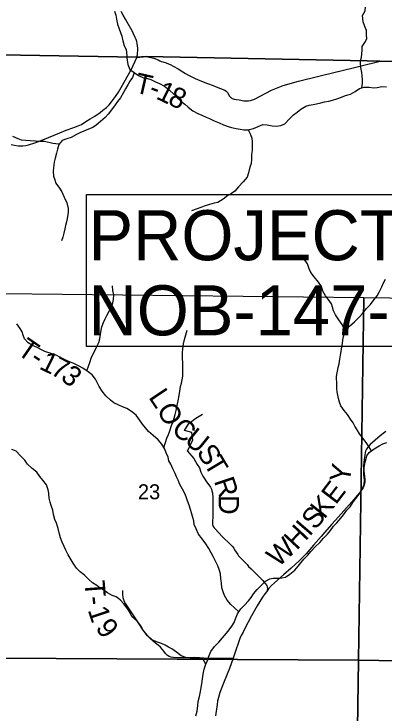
# Model space of a CAD drawing. Extents: x 0 to 34, y -8.9 to 22.
# Drawn here: x 24.734 to 25.769, y 10.111 to 12.069 of the extents above; entities that cross this region are included whole.
import ezdxf

# ---------------------------------------------------------------- set-up
doc = ezdxf.new("R2010")
doc.units = 0
for name, color, linetype in [('GM_X_Corporation', 7, 'Continuous'), ('GM_X_County_Road', 7, 'Continuous'), ('GM_X_County_Road_Text', 7, 'Continuous'), ('GM_X_Minor_River', 7, 'Continuous'), ('GM_X_Section_Text', 7, 'Continuous'), ('GM_X_Township_Road', 7, 'Continuous'), ('GM_X_Township_Road_Text', 7, 'Continuous'), ('SH_Masking', 7, 'Continuous'), ('SH_Text', 7, 'Continuous')]:
    doc.layers.add(name, color=color, linetype=linetype)

msp = doc.modelspace()

# ---------------------------------------------------------------- linework, layer by layer
at = {"layer": 'GM_X_Corporation'}
for points in [[(28.8143, 13.904), (23.7167, 13.904), (23.7167, 11.9654), (24.1849, 11.9621), (24.2054, 11.9625), (24.3163, 11.9608), (25.0773, 11.948), (25.1035, 11.9505), (25.7218, 11.9377), (25.7578, 11.9372), (26.2139, 11.9314), (27.1396, 11.9157), (27.9423, 11.8981), (28.2591, 11.8967), (28.3241, 11.8942), (28.4085, 11.8914), (28.4711, 11.8911), (28.692, 11.888), (28.7762, 11.8872), (28.7779, 11.9899), (28.7786, 12.0342), (28.7787, 12.0377), (28.8049, 13.053), (28.8122, 13.7561)], [(28.8143, 13.904), (23.7167, 13.904), (23.7167, 11.9654), (24.1849, 11.9621), (24.2054, 11.9625), (24.3163, 11.9608), (25.0773, 11.948), (25.1035, 11.9505), (25.7218, 11.9377), (25.7578, 11.9372), (26.2139, 11.9314), (27.1396, 11.9157), (27.9423, 11.8981), (28.2591, 11.8967), (28.3241, 11.8942), (28.4085, 11.8914), (28.4711, 11.8911), (28.692, 11.888), (28.7762, 11.8872), (28.7779, 11.9899), (28.7786, 12.0342), (28.7787, 12.0377), (28.8049, 13.053), (28.8122, 13.7561)], [(24.6992, 11.287), (25.7123, 11.2765), (25.698, 10.2614), (24.6816, 10.2678)], [(25.7123, 11.2765), (26.7259, 11.2629), (26.7158, 10.2453), (25.698, 10.2614)], [(24.6816, 10.2678), (25.698, 10.2614), (25.683, 9.2467), (24.6733, 9.2562)], [(25.698, 10.2614), (26.7158, 10.2453), (26.7025, 9.2378), (25.683, 9.2467)]]:
    msp.add_lwpolyline(points, close=True, dxfattribs=at)
for points in [[(27.1396, 11.9157), (26.2139, 11.9314), (25.7578, 11.9372), (25.7218, 11.9377), (25.1035, 11.9505), (25.0773, 11.948), (24.3163, 11.9608), (24.2054, 11.9625), (24.1849, 11.9621), (23.7167, 11.9654), (23.7167, 7.104)], [(27.1396, 11.9157), (26.2139, 11.9314), (25.7578, 11.9372), (25.7218, 11.9377), (25.1035, 11.9505), (25.0773, 11.948), (24.3163, 11.9608), (24.2054, 11.9625), (24.2028, 11.8378), (24.2025, 11.824), (24.2007, 11.7362), (24.1845, 10.7587), (24.1844, 10.755), (24.1596, 9.2636)]]:
    msp.add_lwpolyline(points, dxfattribs=at)
at = {"layer": 'GM_X_County_Road'}
for points in [[(25.0775, 11.9474), (25.0785, 11.9518), (25.079, 11.9551), (25.0795, 11.96), (25.0798, 11.9662), (25.0798, 11.9731), (25.0792, 11.98), (25.0782, 11.9862), (25.077, 11.9917), (25.0751, 11.9977), (25.0728, 12.0036), (25.0684, 12.0132), (25.0639, 12.0221), (25.0506, 12.046), (25.0457, 12.0547), (25.039, 12.0659), (25.0333, 12.0755)], [(24.7258, 11.7037), (24.735, 11.7017), (24.7452, 11.7001), (24.7587, 11.7), (24.7665, 11.7011), (24.7738, 11.7028), (24.7923, 11.7083), (24.8144, 11.7171), (24.8618, 11.7364), (24.8797, 11.7437), (24.9015, 11.7513), (24.9129, 11.7558), (24.9221, 11.7602), (24.9351, 11.7679), (24.9472, 11.7755), (24.9597, 11.7834), (24.9744, 11.7937), (24.9826, 11.7996), (24.9921, 11.807), (24.9995, 11.8148), (25.0068, 11.8235), (25.0179, 11.8385), (25.026, 11.8503), (25.0338, 11.8634), (25.0421, 11.878), (25.0625, 11.9149), (25.0775, 11.9474)], [(25.7739, 10.9017), (25.7586, 10.889), (25.73, 10.8645), (25.7265, 10.8606), (25.7227, 10.8563), (25.7197, 10.8516), (25.7174, 10.8463), (25.7165, 10.8428), (25.7151, 10.8354), (25.7136, 10.8238), (25.7123, 10.8133), (25.7119, 10.806), (25.7119, 10.8007), (25.7127, 10.7914), (25.7149, 10.7756), (25.7155, 10.7682), (25.7158, 10.7613), (25.7149, 10.755), (25.7131, 10.7489), (25.7108, 10.744), (25.7071, 10.7387), (25.7013, 10.7309), (25.695, 10.7234), (25.6793, 10.705), (25.664, 10.6874), (25.6331, 10.6536), (25.622, 10.6408), (25.6038, 10.6198), (25.593, 10.6077), (25.5714, 10.583), (25.5508, 10.5589), (25.5313, 10.5394), (25.5092, 10.5195), (25.4881, 10.5005), (25.4721, 10.4864), (25.4626, 10.4779), (25.454, 10.4702), (25.4463, 10.4616), (25.4408, 10.4543), (25.4357, 10.4474), (25.4291, 10.4377), (25.4217, 10.4256), (25.4145, 10.414), (25.3987, 10.3862), (25.38, 10.3499), (25.375, 10.3402), (25.3695, 10.3309), (25.3658, 10.3224), (25.35, 10.2755), (25.3472, 10.2677), (25.3365, 10.2388), (25.3221, 10.2017), (25.3099, 10.1713), (25.3057, 10.1573), (25.3035, 10.1468), (25.3018, 10.138), (25.2976, 10.1062)]]:
    msp.add_lwpolyline(points, dxfattribs=at)
at = {"layer": 'GM_X_Minor_River'}
for points in [[(25.7036, 11.9376), (25.7057, 11.9475), (25.7073, 11.9577), (25.7077, 11.9678), (25.7076, 11.978), (25.7158, 11.9895), (25.7206, 11.9995), (25.7197, 12.0112), (25.7203, 12.023), (25.7157, 12.0339), (25.711, 12.0472), (25.7093, 12.065), (25.716, 12.078), (25.717, 12.0897), (25.7154, 12.1003), (25.7149, 12.1125), (25.7106, 12.1231), (25.7056, 12.1348), (25.7043, 12.1454), (25.7016, 12.1567), (25.6966, 12.1673), (25.6953, 12.179), (25.6971, 12.1889), (25.6982, 12.1935)], [(25.0144, 12.0767), (25.0183, 12.0661), (25.0203, 12.0544), (25.0231, 12.0404), (25.0282, 12.0271), (25.0321, 12.0169)], [(25.0321, 12.0169), (25.0352, 12.0067), (25.038, 11.9935), (25.0423, 11.9803), (25.0473, 11.9697), (25.0491, 11.9516), (25.0494, 11.9464)], [(25.0494, 11.9464), (25.0524, 11.928), (25.0574, 11.914), (25.0699, 11.9049), (25.0817, 11.8966), (25.0961, 11.8906), (25.1072, 11.8883), (25.117, 11.8853), (25.1292, 11.8793), (25.141, 11.8744), (25.155, 11.8669), (25.1687, 11.8559), (25.1812, 11.8445), (25.1904, 11.8347), (25.2003, 11.8249), (25.2113, 11.8165), (25.2212, 11.8086), (25.2345, 11.7984), (25.2482, 11.7908), (25.2596, 11.7859), (25.2713, 11.7807), (25.2808, 11.7769), (25.2941, 11.7705), (25.3074, 11.7648), (25.3196, 11.7592), (25.3332, 11.7543), (25.3427, 11.7513), (25.3553, 11.7483), (25.367, 11.7464), (25.3769, 11.745), (25.3898, 11.745), (25.4038, 11.7488), (25.4171, 11.7546), (25.43, 11.76), (25.4418, 11.7589), (25.4562, 11.7562), (25.4672, 11.7551), (25.4805, 11.7575), (25.4918, 11.7613), (25.5043, 11.7758), (25.5161, 11.7865), (25.5263, 11.7945), (25.5361, 11.8032), (25.5501, 11.8109), (25.5596, 11.814), (25.571, 11.8163), (25.5805, 11.8178), (25.5922, 11.8202), (25.6021, 11.8232), (25.6146, 11.8256), (25.6249, 11.8279), (25.6374, 11.8313), (25.6503, 11.8367), (25.6616, 11.8413), (25.6753, 11.8448), (25.6882, 11.8524), (25.7003, 11.8604), (25.7136, 11.8643), (25.728, 11.8639), (25.7397, 11.8628), (25.7496, 11.8636), (25.7633, 11.866), (25.7762, 11.8649)], [(25.707, 11.8624), (25.7086, 11.8753), (25.709, 11.8859), (25.7082, 11.8961), (25.7066, 11.9056), (25.7043, 11.9193), (25.7035, 11.9322), (25.7036, 11.9376)], [(25.0701, 11.9048), (25.0654, 11.8916), (25.0578, 11.8809), (25.0518, 11.8707), (25.0461, 11.8593), (25.0401, 11.849), (25.0314, 11.8349), (25.0231, 11.8242), (25.0166, 11.8147), (25.0064, 11.801), (24.9973, 11.7892), (24.9883, 11.7797), (24.9761, 11.7686), (24.964, 11.7583), (24.9546, 11.7511), (24.9421, 11.7465), (24.9292, 11.7415), (24.9182, 11.7369), (24.9087, 11.7315), (24.8939, 11.7235), (24.8818, 11.72), (24.8681, 11.7151), (24.8591, 11.704), (24.8557, 11.6911), (24.8523, 11.6797), (24.8485, 11.6656), (24.8459, 11.6546), (24.8437, 11.6398), (24.8429, 11.6288), (24.8441, 11.6155), (24.8475, 11.6048), (24.8506, 11.5954), (24.8605, 11.5821), (24.8673, 11.5715), (24.8738, 11.5567), (24.8815, 11.5411), (24.8849, 11.5248), (24.8849, 11.5149), (24.8835, 11.5013), (24.8808, 11.4876), (24.8774, 11.4777), (24.8756, 11.4682), (24.8729, 11.4564), (24.8699, 11.445), (24.8665, 11.4344)], [(24.8594, 11.7045), (24.8427, 11.7066), (24.8188, 11.7119), (24.8055, 11.7122), (24.7934, 11.7133), (24.7793, 11.7144), (24.7547, 11.7162), (24.7452, 11.7196), (24.73, 11.7267)], [(25.3894, 11.745), (25.3955, 11.7321), (25.3993, 11.7215), (25.4005, 11.7112), (25.4005, 11.6991), (25.3998, 11.6873), (25.3987, 11.6763), (25.398, 11.6622), (25.3969, 11.6504), (25.3938, 11.6406), (25.3897, 11.6246), (25.3863, 11.6128), (25.375, 11.5991), (25.3621, 11.5854), (25.3515, 11.5739), (25.342, 11.5667), (25.3318, 11.5617), (25.3193, 11.5514), (25.3042, 11.5422), (25.2939, 11.5403), (25.2806, 11.5357), (25.2662, 11.5315), (25.2564, 11.528), (25.2431, 11.5234), (25.2302, 11.5188)], [(25.6601, 11.1816), (25.6522, 11.2008), (25.6427, 11.2136), (25.6335, 11.2277), (25.6282, 11.239), (25.6248, 11.2489), (25.6221, 11.2588), (25.6129, 11.2713), (25.6053, 11.2811), (25.5977, 11.294), (25.5943, 11.3073), (25.5855, 11.3194), (25.5737, 11.3335), (25.5646, 11.3456), (25.5592, 11.3562), (25.5546, 11.3703), (25.547, 11.3824), (25.5375, 11.3953)], [(25.734, 10.8471), (25.7297, 10.8549), (25.721, 10.8682), (25.7111, 10.8814), (25.7008, 10.8947), (25.6939, 10.9057), (25.6875, 10.9159), (25.6825, 10.9258), (25.6756, 10.936), (25.6665, 10.9485), (25.6574, 10.9603), (25.6486, 10.9732), (25.6448, 10.983), (25.6417, 10.9933), (25.6398, 11.0028), (25.6383, 11.0123), (25.6371, 11.0218), (25.6367, 11.0324), (25.6366, 11.0552), (25.6408, 11.0803), (25.6434, 11.0902), (25.6456, 11.1038), (25.6475, 11.1149), (25.649, 11.1255), (25.6512, 11.1381), (25.6527, 11.1476), (25.6542, 11.1575), (25.6557, 11.167), (25.6602, 11.1822), (25.6727, 11.1959), (25.6863, 11.2081), (25.7003, 11.2218), (25.7087, 11.2313), (25.7204, 11.2451), (25.731, 11.2565), (25.7416, 11.2702), (25.7495, 11.2809), (25.7563, 11.2927), (25.7627, 11.306), (25.768, 11.3167), (25.7729, 11.3269)], [(24.9373, 11.0709), (24.9422, 11.0844), (24.9456, 11.0943), (24.9508, 11.1091), (24.9576, 11.1232), (24.9648, 11.1369), (24.9712, 11.1506), (24.9738, 11.1601), (24.9761, 11.1722), (24.9772, 11.1848), (24.9795, 11.1943), (24.9844, 11.2065), (24.9885, 11.2163), (24.9938, 11.2259), (24.9995, 11.2377), (25.0063, 11.2506), (25.01, 11.2609), (25.0119, 11.2708), (25.0126, 11.2833), (25.0099, 11.2958), (25.0091, 11.3087)], [(25.363, 10.397), (25.3503, 10.4084), (25.3404, 10.4175), (25.3301, 10.4296), (25.3225, 10.4425), (25.3187, 10.4531), (25.3156, 10.4641), (25.314, 10.4782), (25.3125, 10.4895), (25.3113, 10.5028), (25.3079, 10.5154), (25.3041, 10.5256), (25.2972, 10.5385), (25.2907, 10.5518), (25.2854, 10.5616), (25.2785, 10.5745), (25.2701, 10.5874), (25.2602, 10.6011), (25.25, 10.6143), (25.2431, 10.6287), (25.2374, 10.6409), (25.2366, 10.6511), (25.2343, 10.6606), (25.2308, 10.6739), (25.2274, 10.6834), (25.2239, 10.6952), (25.2194, 10.7073), (25.2155, 10.7187), (25.2117, 10.7282), (25.2052, 10.7399), (25.198, 10.7532), (25.1927, 10.765), (25.1888, 10.7744), (25.1843, 10.7839), (25.1782, 10.7972), (25.1724, 10.8101), (25.1671, 10.8196), (25.1648, 10.8294), (25.1594, 10.842), (25.1556, 10.8515), (25.1472, 10.8659), (25.1373, 10.878), (25.1233, 10.8905), (25.1103, 10.9014), (25.102, 10.9113), (25.0936, 10.9215), (25.0852, 10.9344), (25.0753, 10.9469), (25.0624, 10.9571), (25.0498, 10.9654), (25.0373, 10.9707), (25.0271, 10.9745), (25.013, 10.9813), (25.0035, 10.9888), (24.9906, 11.0013), (24.9803, 11.0138), (24.9719, 11.0275), (24.9666, 11.0381), (24.962, 11.0476), (24.9525, 11.0601), (24.9414, 11.068), (24.9266, 11.0782), (24.9145, 11.0854), (24.9012, 11.0918), (24.8875, 11.0967), (24.8772, 11.1009), (24.867, 11.1061), (24.8533, 11.1137), (24.8404, 11.1186), (24.8199, 11.1246), (24.8104, 11.1299), (24.7982, 11.1363), (24.7853, 11.142), (24.7731, 11.1491), (24.7632, 11.1605), (24.7591, 11.1704), (24.7564, 11.1798), (24.7507, 11.1897), (24.7415, 11.2022)], [(25.1527, 10.8564), (25.1575, 10.8708), (25.1616, 10.883), (25.1658, 10.8933), (25.1695, 10.9035), (25.1748, 10.918), (25.1786, 10.9283), (25.1823, 10.9382), (25.185, 10.9484), (25.1876, 10.9602), (25.1895, 10.9701), (25.1928, 10.9868), (25.1962, 11.0017), (25.1977, 11.0142), (25.2, 11.0267), (25.2026, 11.0362), (25.2045, 11.0461), (25.206, 11.0556), (25.2059, 11.0929), (25.2051, 11.1058), (25.205, 11.1217), (25.2065, 11.1328), (25.2076, 11.1464), (25.2103, 11.159), (25.2144, 11.1715), (25.2185, 11.1848)], [(25.2702, 10.2505), (25.2751, 10.2611), (25.2778, 10.2706), (25.2845, 10.2862), (25.2951, 10.2996), (25.3065, 10.3125), (25.3175, 10.3243), (25.3281, 10.3373), (25.3356, 10.3468), (25.3436, 10.3571), (25.3496, 10.367), (25.3538, 10.3772), (25.359, 10.3913), (25.3685, 10.405), (25.3791, 10.4153), (25.3901, 10.4279), (25.3973, 10.4374), (25.4041, 10.4469), (25.4143, 10.4599), (25.4249, 10.4705), (25.4374, 10.4831), (25.4499, 10.4896), (25.4593, 10.4908), (25.4726, 10.4908), (25.4829, 10.4916), (25.4931, 10.4943), (25.506, 10.502), (25.5192, 10.5138), (25.5291, 10.5244), (25.5363, 10.5343), (25.5446, 10.5443), (25.5563, 10.5553), (25.5647, 10.566), (25.5771, 10.5793), (25.5893, 10.5907), (25.5995, 10.6026), (25.6112, 10.6144), (25.6191, 10.6247), (25.6282, 10.6365), (25.6369, 10.646), (25.6483, 10.6586), (25.6562, 10.6681), (25.6653, 10.681), (25.674, 10.6906), (25.6819, 10.7027), (25.6906, 10.7138), (25.6997, 10.7264), (25.7076, 10.7404), (25.7133, 10.7534), (25.7144, 10.7663), (25.7125, 10.78), (25.7128, 10.7921), (25.7143, 10.8062), (25.7169, 10.8195), (25.7214, 10.8328), (25.7279, 10.8423), (25.7415, 10.853), (25.7559, 10.861), (25.7661, 10.8664), (25.7771, 10.871)], [(25.2702, 10.2505), (25.2611, 10.2672), (25.2482, 10.2671), (25.2364, 10.2675), (25.2265, 10.2678), (25.2144, 10.2693), (25.2011, 10.2742), (25.1882, 10.284), (25.1756, 10.2938), (25.1657, 10.2984), (25.1562, 10.304), (25.1464, 10.3086), (25.1323, 10.3131), (25.1202, 10.3184), (25.1072, 10.3305), (25.095, 10.346), (25.0893, 10.357), (25.0779, 10.371), (25.0638, 10.3843), (25.0589, 10.3941), (25.0528, 10.4036), (25.0406, 10.4191), (25.0303, 10.4301), (25.0197, 10.4388), (25.0087, 10.443), (24.995, 10.4501), (24.9851, 10.4573), (24.9752, 10.4634), (24.9653, 10.4702), (24.9536, 10.4785), (24.9429, 10.4876), (24.9307, 10.4997), (24.9189, 10.5084), (24.9087, 10.519), (24.8995, 10.533), (24.8911, 10.5467), (24.8851, 10.5561), (24.8786, 10.5698), (24.8744, 10.5796), (24.8686, 10.5914), (24.8633, 10.6043), (24.8606, 10.6138), (24.8568, 10.6301), (24.8522, 10.6445), (24.848, 10.6552), (24.8445, 10.6696), (24.8419, 10.681), (24.8373, 10.6942), (24.835, 10.7041), (24.8323, 10.7151), (24.8311, 10.7284), (24.8296, 10.7379), (24.8246, 10.7519), (24.8143, 10.7648), (24.806, 10.7754), (24.7972, 10.7876), (24.7843, 10.7974), (24.771, 10.8099), (24.7637, 10.8209), (24.7512, 10.8341), (24.7401, 10.8459), (24.728, 10.8508)], [(25.2421, 10.1064), (25.2459, 10.1194), (25.2481, 10.1349), (25.2492, 10.1463), (25.253, 10.16), (25.2556, 10.1745), (25.2571, 10.1855), (25.259, 10.1957), (25.2612, 10.2098), (25.2631, 10.2231), (25.2657, 10.2364), (25.2702, 10.2505)]]:
    msp.add_lwpolyline(points, dxfattribs=at)
at = {"layer": 'GM_X_Township_Road'}
msp.add_line((25.6411, 11.908), (25.758, 11.9367), dxfattribs=at)
for points in [[(25.0775, 11.9474), (25.1037, 11.9499), (25.1252, 11.9454), (25.1372, 11.9404), (25.1421, 11.938), (25.1459, 11.9363), (25.15, 11.9348), (25.1592, 11.9319), (25.1658, 11.9297), (25.1724, 11.9269), (25.1788, 11.9235), (25.1927, 11.9158), (25.2064, 11.9071), (25.2137, 11.9028), (25.2216, 11.8983), (25.2294, 11.8937), (25.2346, 11.8912), (25.2407, 11.8886), (25.258, 11.8814), (25.2755, 11.8746), (25.2906, 11.8687), (25.2996, 11.8651), (25.3111, 11.8605), (25.3233, 11.8557), (25.3273, 11.8534), (25.3296, 11.8514), (25.3311, 11.8492), (25.3346, 11.8431), (25.3361, 11.84), (25.3379, 11.8378), (25.3398, 11.836), (25.3419, 11.8345), (25.3443, 11.833), (25.3466, 11.8319), (25.3501, 11.8308), (25.3559, 11.8299), (25.3636, 11.8287), (25.3764, 11.8264), (25.3827, 11.8259), (25.3902, 11.826), (25.3958, 11.8267), (25.4068, 11.8306), (25.4538, 11.8556), (25.4869, 11.8689), (25.5299, 11.8807), (25.6401, 11.9078), (25.6411, 11.908)], [(25.2192, 10.8462), (25.2343, 10.8783), (25.2313, 10.8984), (25.2112, 10.9044), (25.2232, 10.9234), (25.2423, 10.9385), (25.2614, 10.9495)], [(25.2192, 10.8462), (25.2369, 10.8261), (25.2412, 10.8177), (25.246, 10.809), (25.2524, 10.7994), (25.2567, 10.7873), (25.2592, 10.7816), (25.2619, 10.7762), (25.2636, 10.7738)], [(25.2636, 10.7738), (25.2658, 10.7706), (25.2723, 10.761), (25.2789, 10.7522), (25.2835, 10.7452), (25.2859, 10.7403), (25.2874, 10.7357), (25.2887, 10.7293), (25.2896, 10.7171), (25.2896, 10.7027), (25.2905, 10.6711), (25.2903, 10.6615), (25.2893, 10.6507), (25.2893, 10.6414), (25.2914, 10.6356), (25.2936, 10.6321), (25.2963, 10.6288), (25.3164, 10.6077), (25.3398, 10.5851), (25.3444, 10.5802), (25.3484, 10.5749), (25.3511, 10.5707), (25.3557, 10.5637), (25.3596, 10.5569), (25.3622, 10.5535), (25.3679, 10.5477), (25.3797, 10.5362), (25.3866, 10.529), (25.3898, 10.5242), (25.3972, 10.517), (25.4067, 10.508), (25.4198, 10.4952), (25.43, 10.4842), (25.4362, 10.4766), (25.4411, 10.4705), (25.4424, 10.4665), (25.443, 10.4623), (25.4408, 10.4543)], [(25.3472, 10.2677), (25.3214, 10.2669), (25.297, 10.2667), (25.2762, 10.2668), (25.2647, 10.2676), (25.2529, 10.2687), (25.2397, 10.2689), (25.2331, 10.268), (25.2262, 10.2679), (25.2101, 10.2684), (25.191, 10.2686), (25.1788, 10.2692), (25.1732, 10.2698), (25.1675, 10.2717), (25.163, 10.275), (25.1576, 10.2806), (25.1525, 10.2869), (25.144, 10.2977), (25.1375, 10.3037), (25.1295, 10.3095), (25.1228, 10.3146), (25.1156, 10.321), (25.1074, 10.3295), (25.095, 10.3457), (25.0767, 10.3746), (25.056, 10.4055), (25.0481, 10.4163), (25.0441, 10.4229), (25.0416, 10.4282), (25.0394, 10.4365), (25.0379, 10.4469), (25.0384, 10.4562)]]:
    msp.add_lwpolyline(points, dxfattribs=at)
at = {"layer": 'SH_Masking'}
msp.add_lwpolyline([(24.9369, 11.5643), (26.727, 11.5643), (26.727, 11.1393), (24.9369, 11.1393)], close=True, dxfattribs=at)
at = {"layer": 'SH_Text'}
msp.add_lwpolyline([(26.727, 11.1393), (24.9369, 11.1393), (24.9369, 11.5643), (26.727, 11.5643)], close=True, dxfattribs=at)

# ---------------------------------------------------------------- texts
at = {"layer": 'GM_X_County_Road_Text'}
for s, rotation, p in [('Y', 80.2604, (25.6719, 10.7554)), ('E', 52.6032, (25.6342, 10.6945)), ('K', 51.3297, (25.6021, 10.6543)), ('S', 49.6738, (25.5762, 10.6237)), ('I', 49.2491, (25.5606, 10.6057)), ('H', 46.8848, (25.5248, 10.5673)), ('W', 42.6321, (25.473, 10.5195))]:
    msp.add_text(s, height=0.0568, rotation=rotation, dxfattribs=at).set_placement(p)
at = {"layer": 'GM_X_Section_Text'}
msp.add_text('23', height=0.04186, rotation=0, dxfattribs=at).set_placement((25.0805, 10.7118))
at = {"layer": 'GM_X_Township_Road_Text'}
for s, rotation, p in [('T', 347.2039, (25.0683, 11.85)), ('1', 334.2402, (25.1284, 11.8335)), ('8', 335.6277, (25.1613, 11.8177)), ('-', 339.5801, (25.1079, 11.8411)), ('T', 325.2674, (24.7392, 11.12)), ('1', 333.8217, (24.8015, 11.0781)), ('-', 326.1542, (24.7749, 11.0952)), ('7', 332.9742, (24.8327, 11.0627)), ('3', 320.7794, (24.8612, 11.0486)), ('L', 303.866, (25.1086, 10.9971)), ('O', 299.1937, (25.1316, 10.9628)), ('C', 320.9281, (25.1711, 10.9013)), ('U', 321.1905, (25.2075, 10.8717)), ('S', 301.614, (25.2431, 10.8442)), ('T', 301.0064, (25.2631, 10.8117)), ('R', 288.2239, (25.2926, 10.7633)), ('D', 270.1603, (25.3064, 10.7236)), ('T', 274.685, (24.9305, 10.4825)), ('-', 276.2026, (24.9341, 10.4385)), ('1', 288.4214, (24.9394, 10.4024)), ('9', 306.9217, (24.9597, 10.3516))]:
    msp.add_text(s, height=0.0568, rotation=rotation, dxfattribs=at).set_placement(p)
at = {"layer": 'SH_Text'}
for s, p in [('PROJECT LOCATION', (24.942, 11.3802)), ('NOB-147-18.42', (24.942, 11.1702))]:
    msp.add_text(s, height=0.14, dxfattribs=at).set_placement(p)

doc.saveas('drawing.dxf')
